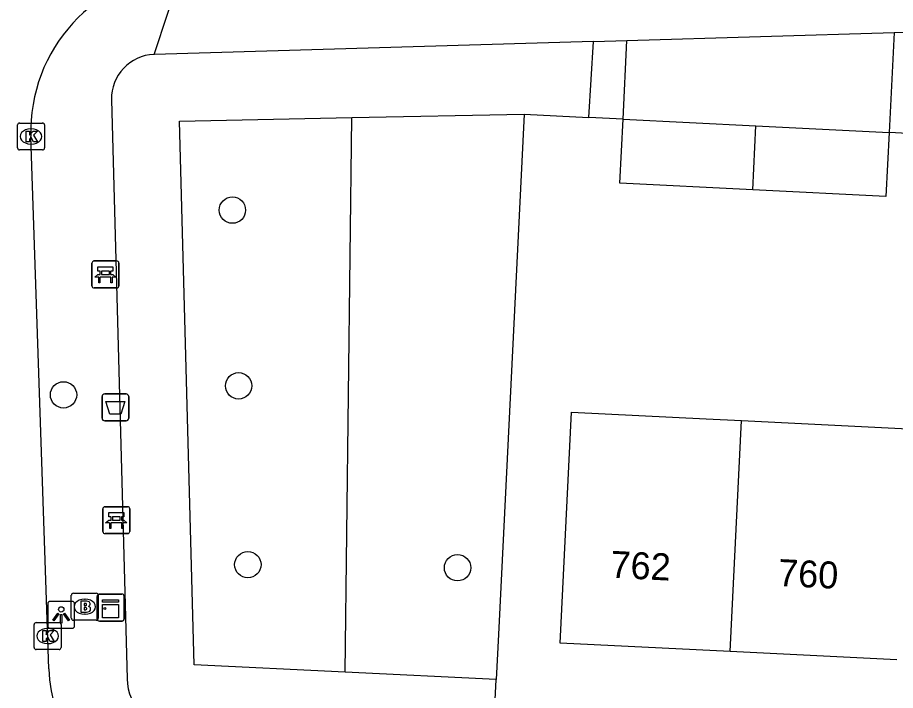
# Model space of a CAD drawing. Extents: x 161253 to 161848, y 384872 to 385383.
# Drawn here: x 161651.31 to 161683.89, y 385329.27 to 385354.25 of the extents above; entities that cross this region are included whole.
import ezdxf

# ---------------------------------------------------------------- set-up
doc = ezdxf.new("R2010")
doc.units = 0
for name, color, linetype in [('IMGEO_Afvalbak', 7, 'Continuous'), ('IMGEO_Bank', 7, 'Continuous'), ('IMGEO_Boom', 7, 'Continuous'), ('IMGEO_Brandkraan', 7, 'Continuous'), ('IMGEO_Groenvoorziening', 7, 'Continuous'), ('IMGEO_Kast', 7, 'Continuous'), ('IMGEO_Kolk', 7, 'Continuous'), ('IMGEO_Lichtpunt', 7, 'Continuous'), ('IMGEO_Pand', 7, 'Continuous'), ('IMGEO_Pand_nummerreeks', 7, 'Continuous'), ('IMGEO_Rijbaan_lokaal_open', 7, 'Continuous'), ('IMGEO_Voetpad_open', 7, 'Continuous')]:
    doc.layers.add(name, color=color, linetype=linetype)

msp = doc.modelspace()

# ---------------------------------------------------------------- linework, layer by layer
at = {"layer": 'IMGEO_Afvalbak'}
for p, q in [((161654.547, 385340.279), (161655.337, 385340.279)), ((161655.337, 385340.279), (161654.547, 385340.279)), ((161654.447, 385339.379), (161654.447, 385340.179)), ((161654.447, 385340.179), (161654.447, 385339.379)), ((161655.437, 385340.179), (161655.437, 385339.379)), ((161655.437, 385339.379), (161655.437, 385340.179)), ((161655.337, 385339.279), (161654.547, 385339.279)), ((161654.547, 385339.279), (161655.337, 385339.279))]:
    msp.add_line(p, q, dxfattribs=at)
msp.add_lwpolyline([(161654.59, 385339.993), (161655.294, 385339.993), (161655.145, 385339.523), (161654.739, 385339.523), (161654.59, 385339.993)], dxfattribs=at)
for centre, start, end in [((161654.547, 385340.179), 90, 180), ((161654.547, 385340.179), 90, 180), ((161655.337, 385340.179), 0, 90), ((161655.337, 385340.179), 360, 90), ((161654.547, 385339.379), 180, 270), ((161654.547, 385339.379), 180, 270), ((161655.337, 385339.379), 270, 0), ((161655.337, 385339.379), 270, 0)]:
    msp.add_arc(centre, 0.1, start, end, dxfattribs=at)
at = {"layer": 'IMGEO_Bank'}
for p, q in [((161654.07, 385344.287), (161654.07, 385345.128)), ((161654.07, 385345.128), (161654.07, 385344.287)), ((161654.145, 385345.212), (161654.986, 385345.212)), ((161654.986, 385345.212), (161654.145, 385345.212)), ((161655.07, 385345.137), (161655.07, 385344.296)), ((161655.07, 385344.296), (161655.07, 385345.137)), ((161654.379, 385344.718), (161654.379, 385344.824)), ((161654.423, 385344.824), (161654.423, 385344.718)), ((161654.711, 385344.83), (161654.429, 385344.83)), ((161654.717, 385344.718), (161654.717, 385344.824)), ((161654.761, 385344.824), (161654.761, 385344.718)), ((161654.767, 385344.61), (161654.374, 385344.61)), ((161654.429, 385344.712), (161654.711, 385344.712)), ((161654.995, 385344.212), (161654.154, 385344.212)), ((161654.154, 385344.212), (161654.995, 385344.212)), ((161654.474, 385335.167), (161654.474, 385336.008)), ((161654.474, 385336.008), (161654.474, 385335.167)), ((161654.549, 385336.092), (161655.39, 385336.092)), ((161655.39, 385336.092), (161654.549, 385336.092)), ((161655.474, 385336.017), (161655.474, 385335.176)), ((161655.474, 385335.176), (161655.474, 385336.017)), ((161654.783, 385335.598), (161654.783, 385335.704)), ((161654.827, 385335.704), (161654.827, 385335.598)), ((161655.115, 385335.71), (161654.833, 385335.71)), ((161655.121, 385335.598), (161655.121, 385335.704)), ((161655.165, 385335.704), (161655.165, 385335.598)), ((161655.171, 385335.49), (161654.778, 385335.49)), ((161654.833, 385335.592), (161655.115, 385335.592)), ((161655.399, 385335.092), (161654.558, 385335.092)), ((161654.558, 385335.092), (161655.399, 385335.092))]:
    msp.add_line(p, q, dxfattribs=at)
for points in [[(161654.373, 385344.83), (161654.287, 385344.83), (161654.287, 385344.991), (161654.85, 385344.991), (161654.85, 385344.83), (161654.767, 385344.83)], [(161654.317, 385344.61), (161654.175, 385344.61), (161654.287, 385344.712), (161654.373, 385344.712)], [(161654.367, 385344.603), (161654.367, 385344.396), (161654.324, 385344.396), (161654.324, 385344.603)], [(161654.767, 385344.712), (161654.85, 385344.712), (161654.962, 385344.61), (161654.823, 385344.61)], [(161654.817, 385344.603), (161654.817, 385344.396), (161654.773, 385344.396), (161654.773, 385344.603)], [(161654.777, 385335.71), (161654.691, 385335.71), (161654.691, 385335.871), (161655.254, 385335.871), (161655.254, 385335.71), (161655.171, 385335.71)], [(161654.721, 385335.49), (161654.579, 385335.49), (161654.691, 385335.592), (161654.777, 385335.592)], [(161654.771, 385335.483), (161654.771, 385335.276), (161654.728, 385335.276), (161654.728, 385335.483)], [(161655.171, 385335.592), (161655.254, 385335.592), (161655.366, 385335.49), (161655.227, 385335.49)], [(161655.221, 385335.483), (161655.221, 385335.276), (161655.177, 385335.276), (161655.177, 385335.483)]]:
    msp.add_lwpolyline(points, dxfattribs=at)
for centre, radius, start, end in [((161654.148, 385345.134), 0.0779, 92.4484, 184.2845), ((161654.148, 385345.134), 0.0779, 92.4484, 184.2845), ((161654.992, 385345.134), 0.0779, 2.4484, 94.2845), ((161654.992, 385345.134), 0.0779, 2.4484, 94.2845), ((161654.372, 385344.823), 0.00671, 2.8957, 87.1043), ((161654.429, 385344.823), 0.00671, 92.8957, 177.1043), ((161654.711, 385344.823), 0.00671, 2.8957, 87.1043), ((161654.768, 385344.823), 0.00671, 92.8957, 177.1043), ((161654.317, 385344.603), 0.00671, 2.8957, 87.1043), ((161654.374, 385344.603), 0.00671, 92.8957, 177.1043), ((161654.372, 385344.719), 0.00671, 272.8957, 357.1043), ((161654.429, 385344.719), 0.00671, 182.8957, 267.1043), ((161654.711, 385344.719), 0.00671, 272.8957, 357.1043), ((161654.768, 385344.719), 0.00671, 182.8957, 267.1043), ((161654.766, 385344.603), 0.00671, 2.8957, 87.1043), ((161654.823, 385344.603), 0.00671, 92.8957, 177.1043), ((161654.148, 385344.29), 0.0779, 182.4484, 274.2845), ((161654.148, 385344.29), 0.0779, 182.4484, 274.2845), ((161654.992, 385344.29), 0.0779, 272.4484, 4.2845), ((161654.992, 385344.29), 0.0779, 272.4484, 4.2845), ((161654.552, 385336.014), 0.0779, 92.4484, 184.2845), ((161654.552, 385336.014), 0.0779, 92.4484, 184.2845), ((161655.396, 385336.014), 0.0779, 2.4484, 94.2845), ((161655.396, 385336.014), 0.0779, 2.4484, 94.2845), ((161654.776, 385335.703), 0.00671, 2.8957, 87.1043), ((161654.833, 385335.703), 0.00671, 92.8957, 177.1043), ((161655.115, 385335.703), 0.00671, 2.8957, 87.1043), ((161655.172, 385335.703), 0.00671, 92.8957, 177.1043), ((161654.721, 385335.483), 0.00671, 2.8957, 87.1043), ((161654.778, 385335.483), 0.00671, 92.8957, 177.1043), ((161654.776, 385335.599), 0.00671, 272.8957, 357.1043), ((161654.833, 385335.599), 0.00671, 182.8957, 267.1043), ((161655.115, 385335.599), 0.00671, 272.8957, 357.1043), ((161655.172, 385335.599), 0.00671, 182.8957, 267.1043), ((161655.17, 385335.483), 0.00671, 2.8957, 87.1043), ((161655.227, 385335.483), 0.00671, 92.8957, 177.1043), ((161654.552, 385335.17), 0.0779, 182.4484, 274.2845), ((161654.552, 385335.17), 0.0779, 182.4484, 274.2845), ((161655.396, 385335.17), 0.0779, 272.4484, 4.2845), ((161655.396, 385335.17), 0.0779, 272.4484, 4.2845)]:
    msp.add_arc(centre, radius, start, end, dxfattribs=at)
at = {"layer": 'IMGEO_Boom'}
for centre in [(161659.284, 385347.101), (161659.513, 385340.578), (161653.015, 385340.243), (161659.856, 385333.94), (161667.639, 385333.825)]:
    msp.add_circle(centre, 0.489, dxfattribs=at)
at = {"layer": 'IMGEO_Brandkraan'}
for p, q in [((161653.305, 385331.953), (161653.305, 385332.805)), ((161653.38, 385332.879), (161654.232, 385332.879)), ((161654.306, 385332.805), (161654.306, 385331.953)), ((161653.793, 385332.659), (161653.818, 385332.659)), ((161653.816, 385332.099), (161653.791, 385332.099)), ((161654.232, 385331.879), (161653.38, 385331.879))]:
    msp.add_line(p, q, dxfattribs=at)
for points in [[(161653.305, 385331.953), (161653.305, 385332.805)], [(161653.38, 385332.879), (161654.232, 385332.879)], [(161654.306, 385332.805), (161654.306, 385331.953)], [(161653.653, 385332.579), (161653.653, 385332.179), (161653.866, 385332.179)], [(161653.884, 385332.579), (161653.653, 385332.579)], [(161653.832, 385332.498), (161653.778, 385332.498), (161653.778, 385332.422)], [(161653.778, 385332.422), (161653.831, 385332.422)], [(161653.84, 385332.346), (161653.778, 385332.346), (161653.778, 385332.265)], [(161653.778, 385332.265), (161653.84, 385332.265)], [(161654.232, 385331.879), (161653.38, 385331.879)]]:
    msp.add_lwpolyline(points, dxfattribs=at)
for centre, radius, start, end in [((161653.382, 385332.803), 0.0765, 91.552, 178.448), ((161653.382, 385332.803), 0.0765, 91.552, 178.448), ((161654.23, 385332.803), 0.0765, 1.552, 88.448), ((161654.23, 385332.803), 0.0765, 1.552, 88.448), ((161653.833, 385332.46), 0.0379, 267.8285, 90.9355), ((161653.888, 385332.434), 0.145, 59.4692, 91.5367), ((161653.913, 385332.481), 0.0922, 285.5137, 58.1501), ((161653.841, 385332.305), 0.0404, 269.8759, 90.5077), ((161653.872, 385332.43), 0.251, 268.6676, 293.5347), ((161653.918, 385332.289), 0.105, 301.3115, 78.989), ((161653.382, 385331.955), 0.0765, 181.552, 268.448), ((161653.382, 385331.955), 0.0765, 181.552, 268.448), ((161654.23, 385331.955), 0.0765, 271.552, 358.448), ((161654.23, 385331.955), 0.0765, 271.552, 358.448)]:
    msp.add_arc(centre, radius, start, end, dxfattribs=at)
for centre, major_axis, ratio, start_param, end_param in [((161653.792, 385332.379), (-0.387, 0.002), 0.722429, 4.712389, 7.853982), ((161653.817, 385332.379), (-0.39, 0.002), 0.717154, 1.570796, 4.712389)]:
    msp.add_ellipse(centre, major_axis=major_axis, ratio=ratio, start_param=start_param, end_param=end_param, dxfattribs=at)
at = {"layer": 'IMGEO_Groenvoorziening'}
for points in [[(161672.517, 385350.541), (161672.684, 385353.364)], [(161673.782, 385350.478), (161673.926, 385353.401)], [(161663.713, 385350.533), (161670.107, 385350.661)], [(161670.107, 385350.661), (161669.158, 385331.351), (161669.076, 385329.674)], [(161670.107, 385350.661), (161672.517, 385350.541)], [(161663.469, 385329.947), (161657.862, 385330.221), (161657.315, 385350.405), (161663.713, 385350.533)], [(161663.469, 385329.947), (161663.713, 385350.533)], [(161673.782, 385350.478), (161672.517, 385350.541)], [(161669.076, 385329.674), (161663.469, 385329.947)], [(161668.953, 385327.177), (161669.076, 385329.674)]]:
    msp.add_lwpolyline(points, dxfattribs=at)
at = {"layer": 'IMGEO_Kast'}
for p, q in [((161654.266, 385331.921), (161654.266, 385332.762)), ((161654.266, 385332.762), (161654.266, 385331.921)), ((161654.341, 385332.846), (161655.182, 385332.846)), ((161655.182, 385332.846), (161654.341, 385332.846)), ((161655.266, 385332.771), (161655.266, 385331.93)), ((161655.266, 385331.93), (161655.266, 385332.771)), ((161655.191, 385331.846), (161654.35, 385331.846)), ((161654.35, 385331.846), (161655.191, 385331.846))]:
    msp.add_line(p, q, dxfattribs=at)
for points in [[(161654.461, 385332.636), (161655.061, 385332.636), (161655.061, 385332.551), (161654.461, 385332.551), (161654.461, 385332.636)], [(161654.461, 385332.461), (161655.061, 385332.461), (161655.061, 385331.972), (161654.461, 385331.972), (161654.461, 385332.461)]]:
    msp.add_lwpolyline(points, dxfattribs=at)
msp.add_circle((161654.545, 385332.31), 0.0377, dxfattribs=at)
for centre, start, end in [((161654.344, 385332.768), 92.4484, 184.2845), ((161654.344, 385332.768), 92.4484, 184.2845), ((161655.188, 385332.768), 2.4484, 94.2845), ((161655.188, 385332.768), 2.4484, 94.2845), ((161654.344, 385331.924), 182.4484, 274.2845), ((161654.344, 385331.924), 182.4484, 274.2845), ((161655.188, 385331.924), 272.4484, 4.2845), ((161655.188, 385331.924), 272.4484, 4.2845)]:
    msp.add_arc(centre, 0.0779, start, end, dxfattribs=at)
at = {"layer": 'IMGEO_Kolk'}
for p, q in [((161651.384, 385350.334), (161652.236, 385350.334)), ((161651.309, 385349.408), (161651.309, 385350.26)), ((161651.797, 385350.114), (161651.822, 385350.114)), ((161652.31, 385350.26), (161652.31, 385349.408)), ((161651.82, 385349.554), (161651.795, 385349.554)), ((161652.236, 385349.334), (161651.384, 385349.334)), ((161652, 385331.79), (161652.852, 385331.79)), ((161651.925, 385330.864), (161651.925, 385331.716)), ((161652.413, 385331.57), (161652.438, 385331.57)), ((161652.926, 385331.716), (161652.926, 385330.864)), ((161652.852, 385330.79), (161652, 385330.79)), ((161652.436, 385331.01), (161652.411, 385331.01))]:
    msp.add_line(p, q, dxfattribs=at)
for points in [[(161651.384, 385350.334), (161652.236, 385350.334)], [(161651.309, 385349.408), (161651.309, 385350.26)], [(161651.63, 385350.034), (161651.753, 385350.034), (161651.753, 385349.883), (161651.883, 385350.034), (161652.047, 385350.034), (161651.901, 385349.883), (161652.054, 385349.634), (161651.902, 385349.634), (161651.817, 385349.798), (161651.753, 385349.731), (161651.753, 385349.634), (161651.63, 385349.634), (161651.63, 385350.034)], [(161652.31, 385350.26), (161652.31, 385349.408)], [(161652.236, 385349.334), (161651.384, 385349.334)], [(161652, 385331.79), (161652.852, 385331.79)], [(161651.925, 385330.864), (161651.925, 385331.716)], [(161652.246, 385331.49), (161652.369, 385331.49), (161652.369, 385331.339), (161652.499, 385331.49), (161652.663, 385331.49), (161652.517, 385331.339), (161652.67, 385331.09), (161652.518, 385331.09), (161652.433, 385331.254), (161652.369, 385331.187), (161652.369, 385331.09), (161652.246, 385331.09), (161652.246, 385331.49)], [(161652.926, 385331.716), (161652.926, 385330.864)], [(161652.852, 385330.79), (161652, 385330.79)]]:
    msp.add_lwpolyline(points, dxfattribs=at)
for centre, start, end in [((161651.386, 385350.258), 91.552, 178.448), ((161651.386, 385350.258), 91.552, 178.448), ((161652.234, 385350.258), 1.552, 88.448), ((161652.234, 385350.258), 1.552, 88.448), ((161651.386, 385349.41), 181.552, 268.448), ((161651.386, 385349.41), 181.552, 268.448), ((161652.234, 385349.41), 271.552, 358.448), ((161652.234, 385349.41), 271.552, 358.448), ((161652.002, 385331.714), 91.552, 178.448), ((161652.002, 385331.714), 91.552, 178.448), ((161652.85, 385331.714), 1.552, 88.448), ((161652.85, 385331.714), 1.552, 88.448), ((161652.002, 385330.866), 181.552, 268.448), ((161652.002, 385330.866), 181.552, 268.448), ((161652.85, 385330.866), 271.552, 358.448), ((161652.85, 385330.866), 271.552, 358.448)]:
    msp.add_arc(centre, 0.0765, start, end, dxfattribs=at)
for centre, major_axis, ratio, start_param, end_param in [((161651.796, 385349.834), (-0.387, 0.002), 0.722429, 4.712389, 7.853982), ((161651.821, 385349.834), (-0.39, 0.002), 0.717154, 1.570796, 4.712389), ((161652.412, 385331.29), (-0.387, 0.002), 0.722429, 4.712389, 7.853982), ((161652.437, 385331.29), (-0.39, 0.002), 0.717154, 1.570796, 4.712389)]:
    msp.add_ellipse(centre, major_axis=major_axis, ratio=ratio, start_param=start_param, end_param=end_param, dxfattribs=at)
at = {"layer": 'IMGEO_Lichtpunt'}
for p, q in [((161652.432, 385332.48), (161652.432, 385331.673)), ((161652.432, 385332.48), (161652.432, 385331.673)), ((161653.334, 385332.575), (161652.526, 385332.575)), ((161653.334, 385332.575), (161652.526, 385332.575)), ((161653.428, 385331.673), (161653.428, 385332.48)), ((161653.428, 385331.673), (161653.428, 385332.48)), ((161652.526, 385331.579), (161653.334, 385331.579)), ((161652.526, 385331.579), (161653.334, 385331.579))]:
    msp.add_line(p, q, dxfattribs=at)
for points in [[(161652.806, 385332.144), (161652.845, 385332.116), (161652.657, 385331.854), (161652.619, 385331.881), (161652.806, 385332.144)], [(161652.908, 385332.096), (161652.955, 385332.096), (161652.955, 385331.774), (161652.908, 385331.774), (161652.908, 385332.096)], [(161653.018, 385332.116), (161653.056, 385332.143), (161653.243, 385331.881), (161653.204, 385331.853), (161653.018, 385332.116)]]:
    msp.add_lwpolyline(points, dxfattribs=at)
msp.add_circle((161652.931, 385332.278), 0.0994, dxfattribs=at)
for centre, start, end in [((161652.526, 385332.48), 90, 180), ((161652.526, 385332.48), 90, 180), ((161653.334, 385332.48), 0, 90), ((161653.334, 385332.48), 0, 90), ((161652.526, 385331.673), 180, 270), ((161652.526, 385331.673), 180, 270), ((161653.334, 385331.673), 270, 0), ((161653.334, 385331.673), 270, 360)]:
    msp.add_arc(centre, 0.0946, start, end, dxfattribs=at)
at = {"layer": 'IMGEO_Pand'}
for points in [[(161678.595, 385347.85), (161673.663, 385348.096), (161673.782, 385350.478)], [(161673.782, 385350.478), (161678.712, 385350.232)], [(161678.595, 385347.85), (161678.712, 385350.232)], [(161678.712, 385350.232), (161683.659, 385349.985)], [(161683.659, 385349.985), (161683.54, 385347.603), (161678.595, 385347.85)], [(161677.756, 385330.714), (161671.446, 385331.024), (161671.867, 385339.598), (161676.861, 385339.353), (161678.176, 385339.288)], [(161677.756, 385330.714), (161678.176, 385339.288)], [(161678.176, 385339.288), (161684.358, 385338.985)], [(161683.937, 385330.411), (161677.756, 385330.714)]]:
    msp.add_lwpolyline(points, dxfattribs=at)
at = {"layer": 'IMGEO_Rijbaan_lokaal_open'}
msp.add_lwpolyline([(161652.465, 385330.074), (161651.808, 385349.838)], dxfattribs=at)
for centre, radius, start, end in [((161657.732, 385350.035), 5.928, 93.2432, 181.9033), ((161657.953, 385330.257), 5.491, 181.9118, 249.1438)]:
    msp.add_arc(centre, radius, start, end, dxfattribs=at)
at = {"layer": 'IMGEO_Voetpad_open'}
for points in [[(161656.378, 385352.878), (161657.397, 385355.953)], [(161673.926, 385353.401), (161683.845, 385353.697)], [(161683.845, 385353.697), (161683.659, 385349.985)], [(161683.845, 385353.697), (161684.655, 385353.721)], [(161672.684, 385353.364), (161656.378, 385352.878)], [(161672.684, 385353.364), (161673.926, 385353.401)], [(161654.793, 385351.195), (161655.375, 385329.707)], [(161686.196, 385349.85), (161683.659, 385349.985)]]:
    msp.add_lwpolyline(points, dxfattribs=at)
for centre, radius, start, end in [((161656.434, 385351.238), 1.641, 91.9471, 181.4882), ((161657.394, 385329.761), 2.02, 181.5397, 224.3575)]:
    msp.add_arc(centre, radius, start, end, dxfattribs=at)

# ---------------------------------------------------------------- texts
at = {"layer": 'IMGEO_Pand_nummerreeks'}
for s, p in [('762', (161673.297, 385333.456)), ('760', (161679.517, 385333.151))]:
    msp.add_text(s, height=1, rotation=357.1892, dxfattribs=at).set_placement(p)

doc.saveas('drawing.dxf')
